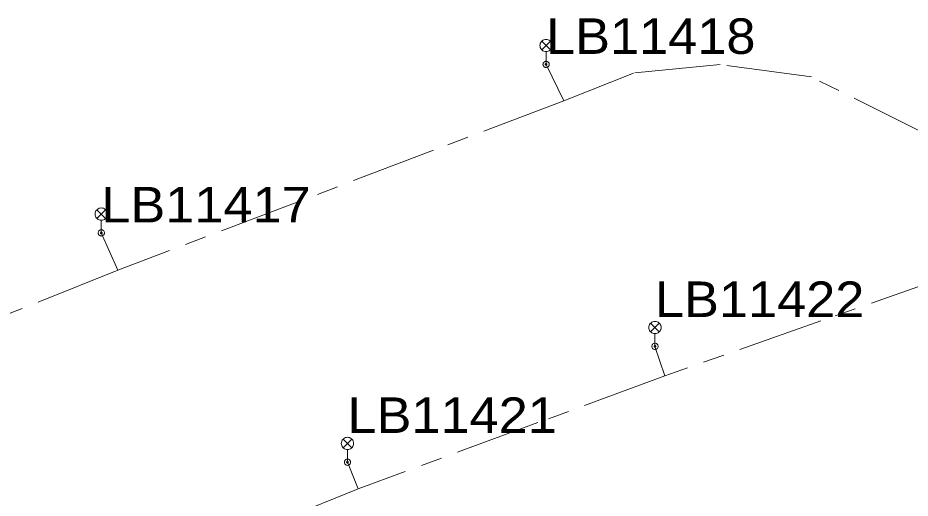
# Model space of a CAD drawing. Extents: x -688049 to -687261, y -973611 to -973038.
# Drawn here: x -687815.7 to -687761.3, y -973328.5 to -973299.2 of the extents above; entities that cross this region are included whole.
import ezdxf

# ---------------------------------------------------------------- set-up
doc = ezdxf.new("R2010")
doc.units = 0
doc.header["$LTSCALE"] = 0.87
doc.linetypes.add('LONG_DASH_SHORT_DASH', pattern=[9.9, 6, -1.2, 1.5, -1.2])
doc.layers.add('1', color=7, linetype='Continuous', lineweight=13)

msp = doc.modelspace()

# ---------------------------------------------------------------- linework, layer by layer
at = {"layer": '1'}
for p, q in [((-687783.795, -973300.635), (-687783.265, -973301.165)), ((-687783.795, -973301.165), (-687783.265, -973300.635)), ((-687783.53, -973302.05), (-687783.53, -973301.275)), ((-687810.915, -973310.915), (-687810.385, -973311.445)), ((-687810.915, -973311.445), (-687810.385, -973310.915)), ((-687810.65, -973312.33), (-687810.65, -973311.555)), ((-687777.155, -973317.835), (-687776.625, -973318.365)), ((-687777.155, -973318.365), (-687776.625, -973317.835)), ((-687776.89, -973319.25), (-687776.89, -973318.475)), ((-687795.905, -973324.905), (-687795.375, -973325.435)), ((-687795.905, -973325.435), (-687795.375, -973324.905)), ((-687795.64, -973326.32), (-687795.64, -973325.545))]:
    msp.add_line(p, q, dxfattribs=at)
at = {"layer": '1', "linetype": 'LONG_DASH_SHORT_DASH'}
for p, q in [((-687782.44, -973304.27), (-687790.386, -973307.289)), ((-687809.65, -973314.61), (-687817.544, -973317.763)), ((-687766.786, -973317.698), (-687776.29, -973321.05)), ((-687784.031, -973323.903), (-687794.99, -973327.94))]:
    msp.add_line(p, q, dxfattribs=at)
at = {"layer": '1'}
for points in [[(-687783.155, -973300.9), (-687783.161, -973300.835), (-687783.178, -973300.772), (-687783.205, -973300.712), (-687783.243, -973300.659), (-687783.289, -973300.613), (-687783.342, -973300.575), (-687783.402, -973300.548), (-687783.465, -973300.531), (-687783.53, -973300.525), (-687783.595, -973300.531), (-687783.658, -973300.548), (-687783.718, -973300.575), (-687783.771, -973300.613), (-687783.817, -973300.659), (-687783.855, -973300.712), (-687783.882, -973300.772), (-687783.899, -973300.835), (-687783.905, -973300.9), (-687783.899, -973300.965), (-687783.882, -973301.028), (-687783.855, -973301.088), (-687783.817, -973301.141), (-687783.771, -973301.187), (-687783.718, -973301.225), (-687783.658, -973301.252), (-687783.595, -973301.269), (-687783.53, -973301.275), (-687783.465, -973301.269), (-687783.402, -973301.252), (-687783.342, -973301.225), (-687783.289, -973301.187), (-687783.243, -973301.141), (-687783.205, -973301.088), (-687783.178, -973301.028), (-687783.161, -973300.965)], [(-687783.34, -973302.05), (-687783.343, -973302.017), (-687783.351, -973301.985), (-687783.365, -973301.955), (-687783.384, -973301.928), (-687783.408, -973301.904), (-687783.435, -973301.885), (-687783.465, -973301.871), (-687783.497, -973301.863), (-687783.53, -973301.86), (-687783.563, -973301.863), (-687783.595, -973301.871), (-687783.625, -973301.885), (-687783.652, -973301.904), (-687783.676, -973301.928), (-687783.695, -973301.955), (-687783.709, -973301.985), (-687783.717, -973302.017), (-687783.72, -973302.05), (-687783.717, -973302.083), (-687783.709, -973302.115), (-687783.695, -973302.145), (-687783.676, -973302.172), (-687783.652, -973302.196), (-687783.625, -973302.215), (-687783.595, -973302.229), (-687783.563, -973302.237), (-687783.53, -973302.24), (-687783.497, -973302.237), (-687783.465, -973302.229), (-687783.435, -973302.215), (-687783.408, -973302.196), (-687783.384, -973302.172), (-687783.365, -973302.145), (-687783.351, -973302.115), (-687783.343, -973302.083)], [(-687783.48, -973302.05), (-687783.481, -973302.041), (-687783.483, -973302.033), (-687783.487, -973302.025), (-687783.492, -973302.018), (-687783.498, -973302.012), (-687783.505, -973302.007), (-687783.513, -973302.003), (-687783.521, -973302.001), (-687783.53, -973302), (-687783.539, -973302.001), (-687783.547, -973302.003), (-687783.555, -973302.007), (-687783.562, -973302.012), (-687783.568, -973302.018), (-687783.573, -973302.025), (-687783.577, -973302.033), (-687783.579, -973302.041), (-687783.58, -973302.05), (-687783.579, -973302.059), (-687783.577, -973302.067), (-687783.573, -973302.075), (-687783.568, -973302.082), (-687783.562, -973302.088), (-687783.555, -973302.093), (-687783.547, -973302.097), (-687783.539, -973302.099), (-687783.53, -973302.1), (-687783.521, -973302.099), (-687783.513, -973302.097), (-687783.505, -973302.093), (-687783.498, -973302.088), (-687783.492, -973302.082), (-687783.487, -973302.075), (-687783.483, -973302.067), (-687783.481, -973302.059)], [(-687810.275, -973311.18), (-687810.281, -973311.115), (-687810.298, -973311.052), (-687810.325, -973310.992), (-687810.363, -973310.939), (-687810.409, -973310.893), (-687810.462, -973310.855), (-687810.522, -973310.828), (-687810.585, -973310.811), (-687810.65, -973310.805), (-687810.715, -973310.811), (-687810.778, -973310.828), (-687810.838, -973310.855), (-687810.891, -973310.893), (-687810.937, -973310.939), (-687810.975, -973310.992), (-687811.002, -973311.052), (-687811.019, -973311.115), (-687811.025, -973311.18), (-687811.019, -973311.245), (-687811.002, -973311.308), (-687810.975, -973311.367), (-687810.937, -973311.421), (-687810.891, -973311.467), (-687810.838, -973311.505), (-687810.778, -973311.532), (-687810.715, -973311.549), (-687810.65, -973311.555), (-687810.585, -973311.549), (-687810.522, -973311.532), (-687810.462, -973311.505), (-687810.409, -973311.467), (-687810.363, -973311.421), (-687810.325, -973311.367), (-687810.298, -973311.308), (-687810.281, -973311.245)], [(-687810.46, -973312.33), (-687810.463, -973312.297), (-687810.471, -973312.265), (-687810.485, -973312.235), (-687810.504, -973312.208), (-687810.528, -973312.184), (-687810.555, -973312.165), (-687810.585, -973312.151), (-687810.617, -973312.143), (-687810.65, -973312.14), (-687810.683, -973312.143), (-687810.715, -973312.151), (-687810.745, -973312.165), (-687810.772, -973312.184), (-687810.796, -973312.208), (-687810.815, -973312.235), (-687810.829, -973312.265), (-687810.837, -973312.297), (-687810.84, -973312.33), (-687810.837, -973312.363), (-687810.829, -973312.395), (-687810.815, -973312.425), (-687810.796, -973312.452), (-687810.772, -973312.476), (-687810.745, -973312.495), (-687810.715, -973312.509), (-687810.683, -973312.517), (-687810.65, -973312.52), (-687810.617, -973312.517), (-687810.585, -973312.509), (-687810.555, -973312.495), (-687810.528, -973312.476), (-687810.504, -973312.452), (-687810.485, -973312.425), (-687810.471, -973312.395), (-687810.463, -973312.363)], [(-687810.6, -973312.33), (-687810.601, -973312.321), (-687810.603, -973312.313), (-687810.607, -973312.305), (-687810.612, -973312.298), (-687810.618, -973312.292), (-687810.625, -973312.287), (-687810.633, -973312.283), (-687810.641, -973312.281), (-687810.65, -973312.28), (-687810.659, -973312.281), (-687810.667, -973312.283), (-687810.675, -973312.287), (-687810.682, -973312.292), (-687810.688, -973312.298), (-687810.693, -973312.305), (-687810.697, -973312.313), (-687810.699, -973312.321), (-687810.7, -973312.33), (-687810.699, -973312.339), (-687810.697, -973312.347), (-687810.693, -973312.355), (-687810.688, -973312.362), (-687810.682, -973312.368), (-687810.675, -973312.373), (-687810.667, -973312.377), (-687810.659, -973312.379), (-687810.65, -973312.38), (-687810.641, -973312.379), (-687810.633, -973312.377), (-687810.625, -973312.373), (-687810.618, -973312.368), (-687810.612, -973312.362), (-687810.607, -973312.355), (-687810.603, -973312.347), (-687810.601, -973312.339)], [(-687776.515, -973318.1), (-687776.521, -973318.035), (-687776.538, -973317.972), (-687776.565, -973317.913), (-687776.603, -973317.859), (-687776.649, -973317.813), (-687776.702, -973317.775), (-687776.762, -973317.748), (-687776.825, -973317.731), (-687776.89, -973317.725), (-687776.955, -973317.731), (-687777.018, -973317.748), (-687777.078, -973317.775), (-687777.131, -973317.813), (-687777.177, -973317.859), (-687777.215, -973317.913), (-687777.242, -973317.972), (-687777.259, -973318.035), (-687777.265, -973318.1), (-687777.259, -973318.165), (-687777.242, -973318.228), (-687777.215, -973318.288), (-687777.177, -973318.341), (-687777.131, -973318.387), (-687777.078, -973318.425), (-687777.018, -973318.452), (-687776.955, -973318.469), (-687776.89, -973318.475), (-687776.825, -973318.469), (-687776.762, -973318.452), (-687776.702, -973318.425), (-687776.649, -973318.387), (-687776.603, -973318.341), (-687776.565, -973318.288), (-687776.538, -973318.228), (-687776.521, -973318.165)], [(-687776.7, -973319.25), (-687776.703, -973319.217), (-687776.711, -973319.185), (-687776.725, -973319.155), (-687776.744, -973319.128), (-687776.768, -973319.104), (-687776.795, -973319.085), (-687776.825, -973319.071), (-687776.857, -973319.063), (-687776.89, -973319.06), (-687776.923, -973319.063), (-687776.955, -973319.071), (-687776.985, -973319.085), (-687777.012, -973319.104), (-687777.036, -973319.128), (-687777.055, -973319.155), (-687777.069, -973319.185), (-687777.077, -973319.217), (-687777.08, -973319.25), (-687777.077, -973319.283), (-687777.069, -973319.315), (-687777.055, -973319.345), (-687777.036, -973319.372), (-687777.012, -973319.396), (-687776.985, -973319.415), (-687776.955, -973319.429), (-687776.923, -973319.437), (-687776.89, -973319.44), (-687776.857, -973319.437), (-687776.825, -973319.429), (-687776.795, -973319.415), (-687776.768, -973319.396), (-687776.744, -973319.372), (-687776.725, -973319.345), (-687776.711, -973319.315), (-687776.703, -973319.283)], [(-687776.84, -973319.25), (-687776.841, -973319.241), (-687776.843, -973319.233), (-687776.847, -973319.225), (-687776.852, -973319.218), (-687776.858, -973319.212), (-687776.865, -973319.207), (-687776.873, -973319.203), (-687776.881, -973319.201), (-687776.89, -973319.2), (-687776.899, -973319.201), (-687776.907, -973319.203), (-687776.915, -973319.207), (-687776.922, -973319.212), (-687776.928, -973319.218), (-687776.933, -973319.225), (-687776.937, -973319.233), (-687776.939, -973319.241), (-687776.94, -973319.25), (-687776.939, -973319.259), (-687776.937, -973319.267), (-687776.933, -973319.275), (-687776.928, -973319.282), (-687776.922, -973319.288), (-687776.915, -973319.293), (-687776.907, -973319.297), (-687776.899, -973319.299), (-687776.89, -973319.3), (-687776.881, -973319.299), (-687776.873, -973319.297), (-687776.865, -973319.293), (-687776.858, -973319.288), (-687776.852, -973319.282), (-687776.847, -973319.275), (-687776.843, -973319.267), (-687776.841, -973319.259)], [(-687795.265, -973325.17), (-687795.271, -973325.105), (-687795.288, -973325.042), (-687795.315, -973324.982), (-687795.353, -973324.929), (-687795.399, -973324.883), (-687795.452, -973324.845), (-687795.512, -973324.818), (-687795.575, -973324.801), (-687795.64, -973324.795), (-687795.705, -973324.801), (-687795.768, -973324.818), (-687795.828, -973324.845), (-687795.881, -973324.883), (-687795.927, -973324.929), (-687795.965, -973324.982), (-687795.992, -973325.042), (-687796.009, -973325.105), (-687796.015, -973325.17), (-687796.009, -973325.235), (-687795.992, -973325.298), (-687795.965, -973325.357), (-687795.927, -973325.411), (-687795.881, -973325.457), (-687795.828, -973325.495), (-687795.768, -973325.522), (-687795.705, -973325.539), (-687795.64, -973325.545), (-687795.575, -973325.539), (-687795.512, -973325.522), (-687795.452, -973325.495), (-687795.399, -973325.457), (-687795.353, -973325.411), (-687795.315, -973325.357), (-687795.288, -973325.298), (-687795.271, -973325.235)], [(-687795.45, -973326.32), (-687795.453, -973326.287), (-687795.461, -973326.255), (-687795.475, -973326.225), (-687795.494, -973326.198), (-687795.518, -973326.174), (-687795.545, -973326.155), (-687795.575, -973326.141), (-687795.607, -973326.133), (-687795.64, -973326.13), (-687795.673, -973326.133), (-687795.705, -973326.141), (-687795.735, -973326.155), (-687795.762, -973326.174), (-687795.786, -973326.198), (-687795.805, -973326.225), (-687795.819, -973326.255), (-687795.827, -973326.287), (-687795.83, -973326.32), (-687795.827, -973326.353), (-687795.819, -973326.385), (-687795.805, -973326.415), (-687795.786, -973326.442), (-687795.762, -973326.466), (-687795.735, -973326.485), (-687795.705, -973326.499), (-687795.673, -973326.507), (-687795.64, -973326.51), (-687795.607, -973326.507), (-687795.575, -973326.499), (-687795.545, -973326.485), (-687795.518, -973326.466), (-687795.494, -973326.442), (-687795.475, -973326.415), (-687795.461, -973326.385), (-687795.453, -973326.353)], [(-687795.59, -973326.32), (-687795.591, -973326.311), (-687795.593, -973326.303), (-687795.597, -973326.295), (-687795.602, -973326.288), (-687795.608, -973326.282), (-687795.615, -973326.277), (-687795.623, -973326.273), (-687795.631, -973326.271), (-687795.64, -973326.27), (-687795.649, -973326.271), (-687795.657, -973326.273), (-687795.665, -973326.277), (-687795.672, -973326.282), (-687795.678, -973326.288), (-687795.683, -973326.295), (-687795.687, -973326.303), (-687795.689, -973326.311), (-687795.69, -973326.32), (-687795.689, -973326.329), (-687795.687, -973326.337), (-687795.683, -973326.345), (-687795.678, -973326.352), (-687795.672, -973326.358), (-687795.665, -973326.363), (-687795.657, -973326.367), (-687795.649, -973326.369), (-687795.64, -973326.37), (-687795.631, -973326.369), (-687795.623, -973326.367), (-687795.615, -973326.363), (-687795.608, -973326.358), (-687795.602, -973326.352), (-687795.597, -973326.345), (-687795.593, -973326.337), (-687795.591, -973326.329)]]:
    msp.add_lwpolyline(points, close=True, dxfattribs=at)
at = {"layer": '1', "linetype": 'LONG_DASH_SHORT_DASH'}
for points in [[(-687735.66, -973318.54), (-687740.76, -973319.15), (-687744.54, -973318.25), (-687745.444, -973318.022), (-687745.799, -973317.745), (-687746.29, -973316.68), (-687746.94, -973314.5), (-687749.17, -973313.57), (-687752.97, -973313.15), (-687755.2, -973310.14), (-687760.08, -973306.45), (-687767.34, -973302.82), (-687772.92, -973302.06), (-687778.2, -973302.58), (-687782.44, -973304.27), (-687783.53, -973302.05)], [(-687790.386, -973307.289), (-687809.65, -973314.61), (-687810.65, -973312.33)], [(-687759.43, -973313.29), (-687758.77, -973314.87), (-687766.786, -973317.698)], [(-687776.89, -973319.25), (-687776.29, -973321.05), (-687784.031, -973323.903)], [(-687795.64, -973326.32), (-687794.99, -973327.94), (-687799.628, -973329.809)]]:
    msp.add_lwpolyline(points, dxfattribs=at)

# ---------------------------------------------------------------- texts
at = {"layer": '1', "width": 1.1}
for s, p in [('LB11418', (-687783.53, -973301.412)), ('LB11417', (-687810.65, -973311.692)), ('LB11422', (-687776.89, -973317.462)), ('LB11421', (-687795.64, -973324.532))]:
    msp.add_text(s, height=2.168, dxfattribs=at).set_placement(p)

doc.saveas('drawing.dxf')
